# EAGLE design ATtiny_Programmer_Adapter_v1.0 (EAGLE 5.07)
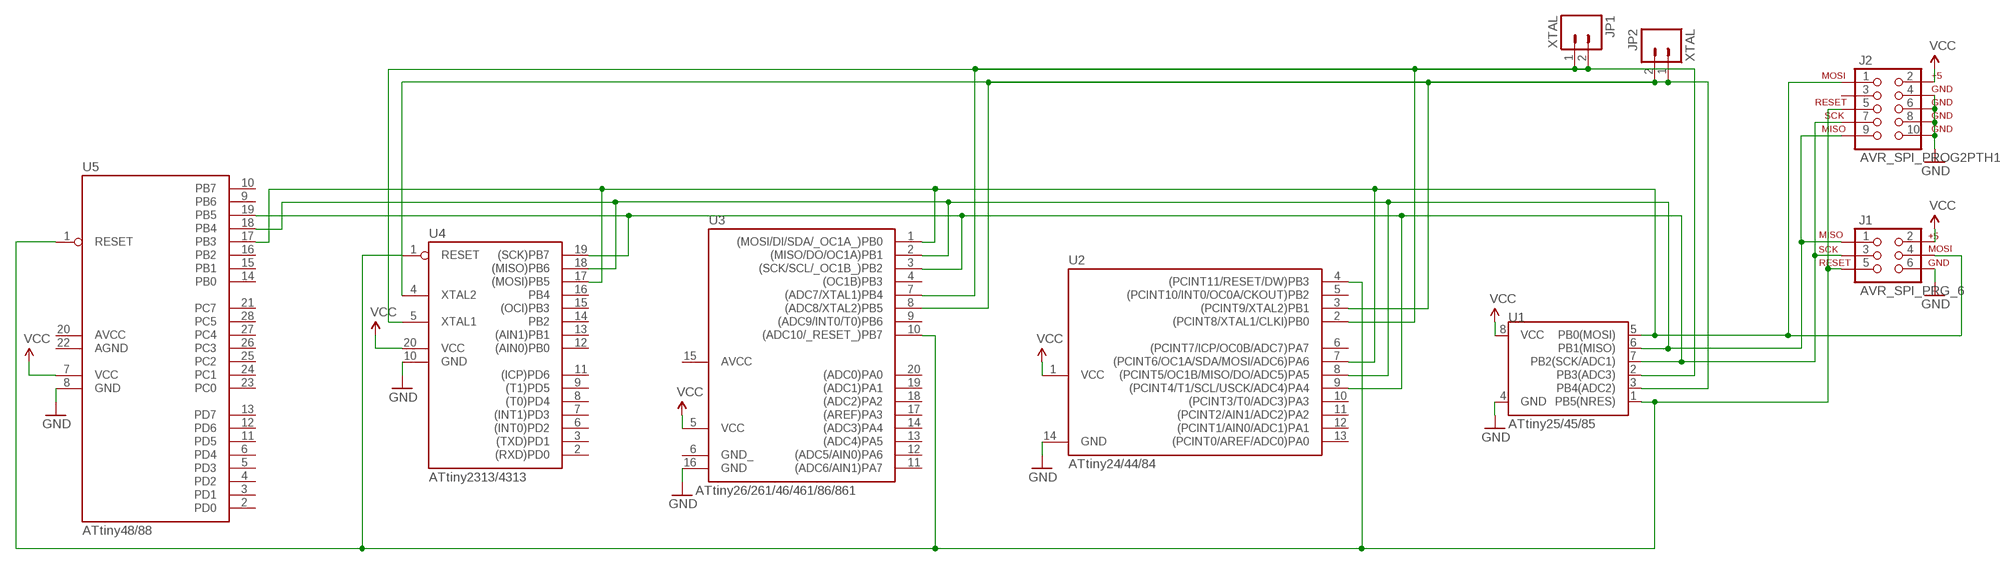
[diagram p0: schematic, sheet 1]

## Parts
J1  AVR_SPI_PRG_6  [2X3_2]
J2  AVR_SPI_PROG2PTH1  [AVR_ICSP_3]
JP1  XTAL  M02PTH  [1X02]
JP2  XTAL  M02PTH  [1X02]
U1  ATtiny25/45/85  ATTINY45DIP8  [DIP08]
U2  ATtiny24/44/84  TINY24/44/84  [DIP14]
U3  ATtiny26/261/46/461/86/861  TINY26  [DIP20]
U4  ATtiny2313/4313  AT90S2313  [DIP20]
U5  ATtiny48/88  TINY48-88DIP28  [DIP28]

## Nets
GND: J1.6 J2.4 J2.6 J2.8 J2.10 U1.4(GND) U2.14(GND) U3.16(GND) U4.10(GND) U5.8(GND)
MISO: J1.1 J2.9 U1.6(PB1(MISO)) U2.8((PCINT5/OC1B/MISO/DO/ADC5)PA5) U3.2((MISO/DO/OC1A)PB1) U4.18((MISO)PB6) U5.18(PB4)
MOSI: J1.5 J2.5 U1.1(PB5(NRES)) U2.4((PCINT11/RESET/DW)PB3) U3.10((ADC10/_RESET_)PB7) U4.1(RESET) U5.1(RESET)
N$2: J1.3 J2.7 U1.7(PB2(SCK/ADC1)) U2.9((PCINT4/T1/SCL/USCK/ADC4)PA4) U3.3((SCK/SCL/_OC1B_)PB2) U4.19((SCK)PB7) U5.19(PB5)
N$6: JP1.1 JP1.2 U1.2(PB3(ADC3)) U2.2((PCINT8/XTAL1/CLKI)PB0) U3.7((ADC7/XTAL1)PB4) U4.5(XTAL1)
N$7: J1.4 J2.1 U1.5(PB0(MOSI)) U2.7((PCINT6/OC1A/SDA/MOSI/ADC6)PA6) U3.1((MOSI/DI/SDA/_OC1A_)PB0) U4.17((MOSI)PB5) U5.17(PB3)
N$10: JP2.1 JP2.2 U1.3(PB4(ADC2)) U2.3((PCINT9/XTAL2)PB1) U3.8((ADC8/XTAL2)PB5) U4.4(XTAL2)
VCC: J1.2 J2.2 U1.8(VCC) U2.1(VCC) U3.5(VCC) U4.20(VCC) U5.7(VCC)
Unconnected: J2.3 U2.5((PCINT10/INT0/OC0A/CKOUT)PB2) U2.6((PCINT7/ICP/OC0B/ADC7)PA7) U2.10((PCINT3/T0/ADC3)PA3) U2.11((PCINT2/AIN1/ADC2)PA2) U2.12((PCINT1/AIN0/ADC1)PA1) U2.13((PCINT0/AREF/ADC0)PA0) U3.4((OC1B)PB3) U3.9((ADC9/INT0/T0)PB6) U3.11((ADC6/AIN1)PA7) U3.12((ADC5/AIN0)PA6) U3.13((ADC4)PA5) U3.14((ADC3)PA4) U3.17((AREF)PA3) U3.18((ADC2)PA2) U3.19((ADC1)PA1) U3.20((ADC0)PA0) U4.2((RXD)PD0) U4.3((TXD)PD1) U4.6((INT0)PD2) U4.7((INT1)PD3) U4.8((T0)PD4) U4.9((T1)PD5) U4.11((ICP)PD6) U4.12((AIN0)PB0) U4.13((AIN1)PB1) U4.14(PB2) U4.15((OCI)PB3) U4.16(PB4) U5.2(PD0) U5.3(PD1) U5.4(PD2) U5.5(PD3) U5.6(PD4) U5.9(PB6) U5.10(PB7) U5.11(PD5) U5.12(PD6) U5.13(PD7) U5.14(PB0) U5.15(PB1) U5.16(PB2) U5.21(PC7) U5.23(PC0) U5.24(PC1) U5.25(PC2) U5.26(PC3) U5.27(PC4) U5.28(PC5)

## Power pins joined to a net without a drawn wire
AGND: U5.22(AGND)
AVCC: U3.15(AVCC) U5.20(AVCC)
GND_: U3.6(GND_)

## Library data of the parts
J1 = SparkFun:AVR_SPI_PRG_6: AVR ISP 6 Pin This is the reduced ISP connector for AVR programming. Common on Arduino. This footprint will take up less PCB space and can be used with a 10-pin to 6-pin adapter such as SKU: BOB-08508
J2 = SparkFun:AVR_SPI_PROG2: AVR ICSP Header This is the standard AVR In Circuit Serial Programming header. Minimal, but includes pin one indicator. Works with standard Olimex programmers. Also look for the 6-pin reduced version. Spark Fun Electronics SKU: PRT-00778
JP1 JP2 = SparkFun:M02: Header 2
U1 = SparkFun:ATTINY45: Atmel ATTiny45
U2 = avr-5:TINY24/44/84
U3 = avr-5:TINY26
U4 = avr-5:AT90S2313: MICROCONTROLLER 2 Kbytes FLASH 128 bytes SRAM 128 bytes EEPROM UART
U5 = atmel:TINY48-88

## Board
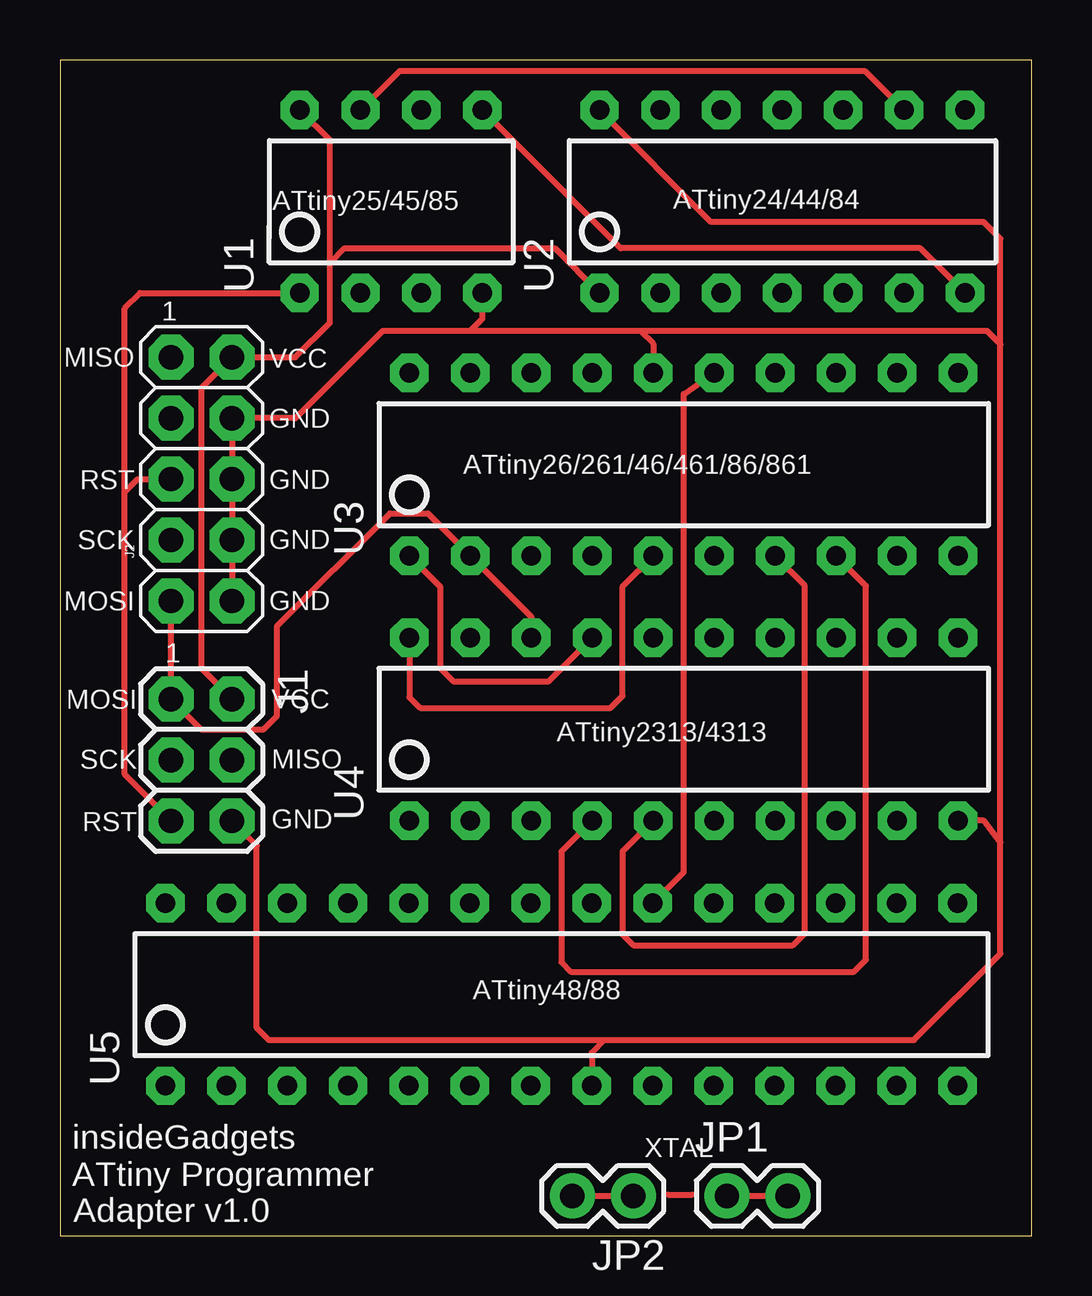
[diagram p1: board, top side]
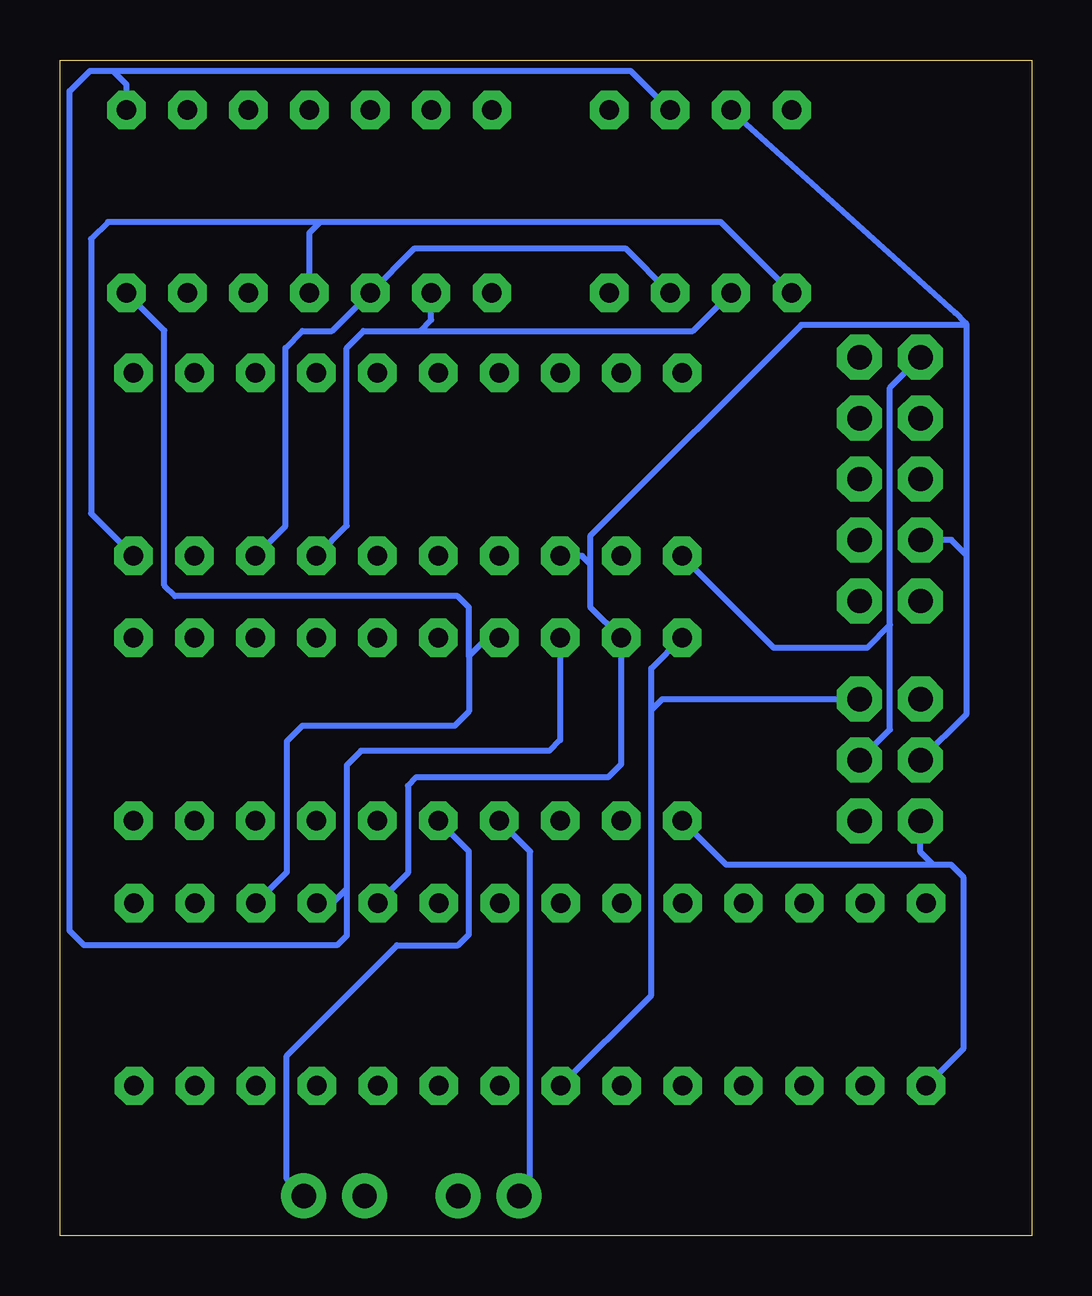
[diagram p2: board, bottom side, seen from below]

Size 40.5 x 49 mm. Coordinates in mm from the lower left corner, seen from the top.
Outline: 0,0 40.5,0 40.5,49 0,49 0,0
Copper layers (1*16): Top 0.035mm / dielectric 1.5mm / Bottom 0.035mm
Design rules "ITead_rule": minimum track width 6mil, minimum drill 12mil, track to track 6mil, track to pad 6mil, pad to pad 6mil, via to via 6mil, smd to smd 0mil, copper to edge 10mil, drill to drill 10mil, minimum pad ring 10mil, minimum via ring 6mil, stop-mask expansion 2mil, vias tented up to drill 100mil, thermal gap 10mil

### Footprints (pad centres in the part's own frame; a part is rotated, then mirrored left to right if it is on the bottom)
2X3_2 = drill 1.016 pad 1.88 octagon: 1 -2.54,-1.27; 2 -2.54,1.27; 3 0,-1.27; 4 0,1.27; 5 2.54,-1.27; 6 2.54,1.27
AVR_ICSP_3 = drill 1.016 pad 1.88 octagon: 1 -1.27,5.08; 2 1.27,5.08; 3 -1.27,2.54; 4 1.27,2.54; 5 -1.27,0; 6 1.27,0; 7 -1.27,-2.54; 8 1.27,-2.54; 9 -1.27,-5.08; 10 1.27,-5.08
1X02 = drill 1.016 pad 1.88 round: 1 0,0; 2 2.54,0
DIP08 = drill 0.813 pad 1.6 octagon: 1 -3.81,-3.81; 2 -1.27,-3.81; 3 1.27,-3.81; 4 3.81,-3.81; 5 3.81,3.81; 6 1.27,3.81; 7 -1.27,3.81; 8 -3.81,3.81
DIP14 = drill 0.813 pad 1.6 octagon: 1 -3.81,-3.81; 2 -1.27,-3.81; 3 1.27,-3.81; 4 3.81,-3.81; 5 6.35,-3.81; 6 8.89,-3.81; 7 11.43,-3.81; 8 11.43,3.81; 9 8.89,3.81; 10 6.35,3.81; 11 3.81,3.81; 12 1.27,3.81; 13 -1.27,3.81; 14 -3.81,3.81
DIP20 = drill 0.813 pad 1.6 octagon: 1 -11.43,-3.81; 2 -8.89,-3.81; 3 -6.35,-3.81; 4 -3.81,-3.81; 5 -1.27,-3.81; 6 1.27,-3.81; 7 3.81,-3.81; 8 6.35,-3.81; 9 8.89,-3.81; 10 11.43,-3.81; 11 11.43,3.81; 12 8.89,3.81; 13 6.35,3.81; 14 3.81,3.81; 15 1.27,3.81; 16 -1.27,3.81; 17 -3.81,3.81; 18 -6.35,3.81; 19 -8.89,3.81; 20 -11.43,3.81
DIP28 = drill 0.813 pad 1.6 octagon: 1 -16.51,-3.81; 2 -13.97,-3.81; 3 -11.43,-3.81; 4 -8.89,-3.81; 5 -6.35,-3.81; 6 -3.81,-3.81; 7 -1.27,-3.81; 8 1.27,-3.81; 9 3.81,-3.81; 10 6.35,-3.81; 11 8.89,-3.81; 12 11.43,-3.81; 13 13.97,-3.81; 14 16.51,-3.81; 15 16.51,3.81; 16 13.97,3.81; 17 11.43,3.81; 18 8.89,3.81; 19 6.35,3.81; 20 3.81,3.81; 21 1.27,3.81; 22 -1.27,3.81; 23 -3.81,3.81; 24 -6.35,3.81; 25 -8.89,3.81; 26 -11.43,3.81; 27 -13.97,3.81; 28 -16.51,3.81

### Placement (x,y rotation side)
J1  5.9,19.82 270 top
J2  5.9,31.53 0 top
JP1  27.8,1.65 0 top
JP2  23.9,1.65 180 top
U1  13.8,43.1 0 top
U2  26.3,43.1 0 top
U3  26,32.14 0 top
U4  26,21.11 0 top
U5  20.9,10.05 0 top

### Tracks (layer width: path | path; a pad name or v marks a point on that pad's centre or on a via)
AVCC
  Top 0.254: U3.15 26,35.08 26,15.15 U5.20
GND
  Top 0.254: U5.8 22.17,7.62 22.7,8.15 | U2.14 27.14,42.25 38.5,42.25 39.2,41.55 39.2,37.15 | U4.10 38.51,17.3 39.2,16.39 | J2.10 J2.8 J2.6 J2.4 9.82,34.07 13.45,37.7 17.1,37.7 | 39.2,16.39 39.2,37.15 | 24.2,37.7 38.65,37.7 39.2,37.15 | 24.2,37.7 17.1,37.7 | U1.4 17.61,38.21 17.1,37.7 | U3.16 24.73,37.17 24.2,37.7 | 22.7,8.15 8.7,8.15 8.2,8.65 8.2,16.25 J1.6 | 39.2,16.39 39.2,11.75 35.6,8.15 22.7,8.15
MISO
  Top 0.254: U4.18 19.65,25.79 U3.2 15.34,30.1 13.75,30.1 9.05,25.4 9.05,21.66 8.49,21.1 5.89,21.1 J1.1 J2.9
  Bottom 0.254: U1.6 16.71,48.55 38.3,48.55 | 38.3,48.55 39.25,48.55 40.1,47.7 40.1,12.7 39.5,12.1 28.95,12.1 28.55,12.5 28.55,14.45 | U2.8 37.73,47.98 38.3,48.55 | U4.18 19.65,20.65 20.1,20.2 27.95,20.2 28.55,19.6 28.55,14.45 | U5.18 29.14,13.86 28.55,14.45
MOSI
  Top 0.254: U1.1 3.34,39.29 2.7,38.65 2.7,31 | J1.5 2.7,19.21 2.7,31 | J2.5 3.23,31.53 2.7,31
  Bottom 0.254: U1.1 12.95,42.25 29.65,42.25 | 29.65,42.25 38.5,42.25 39.2,41.55 39.2,30.1 U3.10 | U2.4 30.11,41.79 29.65,42.25 | U4.1 12.72,15.45 4.1,15.45 | 4.1,15.45 3.35,15.45 2.83,14.93 2.83,7.8 U5.1 | J1.5 4.63,15.98 4.1,15.45
N$2
  Top 0.254: U1.7 14.17,48.55 33.55,48.55 U2.9
  Bottom 0.254: U5.19 26,15.11 26,18.75 25.65,19.1 17.65,19.1 17.11,19.64 U4.19 18.4,26.2 18.4,28 | 2.76,38.04 2.7,37.98 2.7,28.35 | 2.76,38.04 3.19,38.47 U1.7 | J1.3 2.7,21.75 2.7,28.35 | J2.7 3.34,28.99 2.7,28.35 | U3.3 18.73,28.33 18.4,28 | 18.4,28 18.4,29.15 9.6,37.95 2.85,37.95 2.76,38.04
N$6
  Top 0.254: U4.5 23.45,16.02 23.45,12.55 23.9,12.1 30.55,12.1 31.05,12.6 31.05,27.09 U3.7 | JP1.1 JP1.2
  Bottom 0.254: U1.2 14.12,37.7 25.5,37.7 | 25.5,37.7 27.85,37.7 28.55,37 28.55,29.59 U3.7 | U2.2 25.03,38.17 25.5,37.7 | U4.5 23.45,16.02 23.45,12.55 23.9,12.1 26.45,12.1 31.05,7.5 31.05,2.36 JP1.2
N$7
  Top 0.254: U4.17 20.37,23.1 16.4,23.1 15.85,23.65 15.85,27.05 U3.1 | U1.5 23.37,41.15 35.87,41.15 U2.7
  Bottom 0.254: U2.7 36.15,37.72 36.15,27.1 35.7,26.65 23.92,26.65 23.45,26.18 23.45,24.15 | U4.17 22.68,24.92 23.45,24.15 | 23.45,24.15 23.45,21.85 24.05,21.25 30.4,21.25 31.05,20.6 31.05,15.14 U5.17 | U3.1 10.74,24.5 6.85,24.5 5.9,25.45 | J1.4 5.9,21.09 5.9,25.45 | 5.9,25.45 5.9,35.34 J2.1
N$8
  Top 0.254: 25.35,1.7 26.35,1.7
N$10
  Top 0.254: U3.8 33.6,27.08 33.6,11.5 33.1,11 21.3,11 20.9,11.4 20.9,16.01 U4.4 | JP2.2 JP2.1
  Bottom 0.254: U3.8 31.1,29.58 31.1,37 30.4,37.7 29.16,37.7 U2.3 25.71,41.15 16.93,41.15 U1.3 | U4.4 20.9,16.01 20.9,2.11 JP2.2
VCC
  Top 0.254: 11.25,40.6 11.25,38.05 9.81,36.61 J2.2 5.9,35.34 5.9,23.63 J1.2 | 11.25,40.6 11.25,45.65 U1.8 | U2.1 20.63,41.15 11.85,41.15 11.3,40.6 11.25,40.6 | U3.5 23.45,27.05 23.45,22.5 22.95,22 15,22 14.57,22.43 U4.20
  Bottom 0.254: U4.20 15.85,23.64 15.85,21.9 | J1.2 15.39,22.36 15.85,21.9 | U5.7 15.85,10.02 15.85,21.9

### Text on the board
tPlace: ATtiny25/45/85 | ATtiny24/44/84 | 1 | MISO | VCC | GND | RST | GND | ATtiny26/261/46/461/86/861 | SCK | GND | MOSI | GND | 1 | MOSI | VCC | SCK | ATtiny2313/4313 | MISO | RST | GND | ATtiny48/88 | insideGadgets | XTAL | ATtiny Programmer | Adapter v1.0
